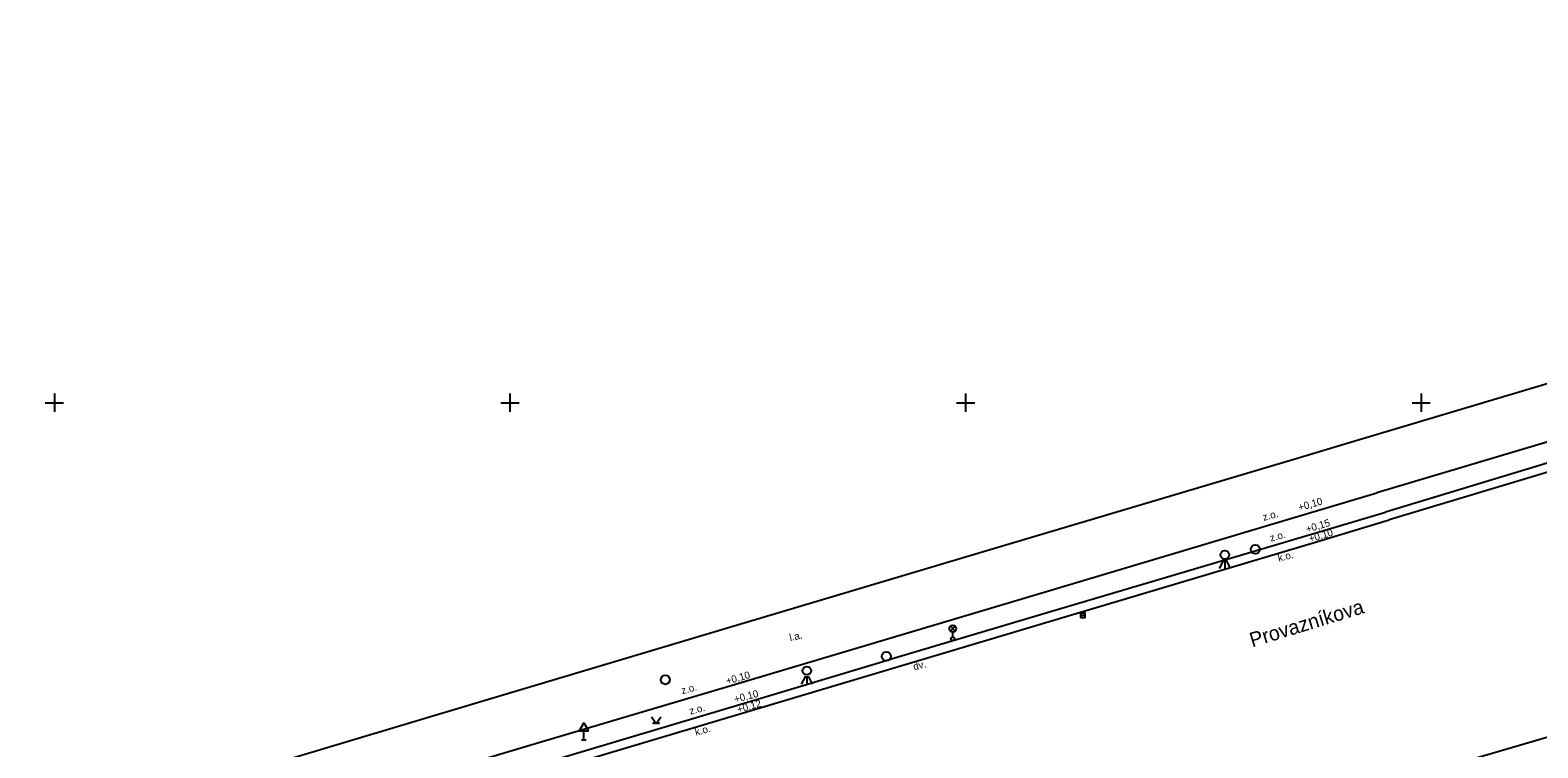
# Model space of a CAD drawing. Extents: x -597333 to -596488, y -1158921 to -1158644.
# Drawn here: x -597201.3 to -597118.6, y -1158843.9 to -1158804.6 of the extents above; entities that cross this region are included whole.
import ezdxf

# ---------------------------------------------------------------- set-up
doc = ezdxf.new("R2010")
doc.units = 0
for name, color, linetype in [('Vrstva 10', 7, 'Continuous'), ('Vrstva 14', 7, 'Continuous'), ('Vrstva 19', 7, 'Continuous'), ('Vrstva 25', 7, 'Continuous'), ('Vrstva 29', 7, 'Continuous'), ('Vrstva 42', 7, 'Continuous'), ('Vrstva 44', 7, 'Continuous'), ('Vrstva 49', 7, 'Continuous'), ('Vrstva 50', 7, 'Continuous'), ('Vrstva 62', 7, 'Continuous'), ('Vrstva 7', 7, 'Continuous')]:
    doc.layers.add(name, color=color, linetype=linetype)

msp = doc.modelspace()

# ---------------------------------------------------------------- linework, layer by layer
at = {"layer": 'Vrstva 10'}
for points in [[(-597131.858, -1158828.063), (-597128.696, -1158827.109), (-597091, -1158815.87), (-597089.946, -1158815.514), (-597071.273, -1158809.949), (-597053.2, -1158804.562)], [(-597163.188, -1158837.385), (-597148.28, -1158832.949), (-597131.858, -1158828.063)], [(-597187.728, -1158844.729), (-597176.909, -1158841.491), (-597163.188, -1158837.385)]]:
    msp.add_lwpolyline(points, dxfattribs=at)
at = {"layer": 'Vrstva 14'}
msp.add_lwpolyline([(-597167.23, -1158842.229), (-597166.98, -1158842.604), (-597166.73, -1158842.229)], dxfattribs=at)
for centre in [(-597167.105, -1158842.579), (-597166.855, -1158842.579)]:
    msp.add_circle(centre, 0.025, dxfattribs=at)
at = {"layer": 'Vrstva 19'}
for p, q in [((-597170.945, -1158842.56), (-597171.195, -1158842.993)), ((-597171.195, -1158842.993), (-597170.695, -1158842.993)), ((-597170.945, -1158842.56), (-597170.695, -1158842.993)), ((-597170.945, -1158843.493), (-597170.945, -1158842.993)), ((-597171.07, -1158843.493), (-597170.82, -1158843.493))]:
    msp.add_line(p, q, dxfattribs=at)
at = {"layer": 'Vrstva 25'}
msp.add_line((-597143.691, -1158836.663), (-597143.441, -1158836.663), dxfattribs=at)
msp.add_lwpolyline([(-597143.691, -1158836.788), (-597143.441, -1158836.788), (-597143.441, -1158836.538), (-597143.691, -1158836.538)], close=True, dxfattribs=at)
for centre in [(-597134.096, -1158833.04), (-597154.347, -1158838.916), (-597166.473, -1158840.201)]:
    msp.add_circle(centre, 0.25, dxfattribs=at)
at = {"layer": 'Vrstva 29'}
for p, q in [((-597150.834, -1158837.526), (-597150.57, -1158837.262)), ((-597150.566, -1158837.525), (-597150.83, -1158837.26)), ((-597150.702, -1158837.857), (-597150.702, -1158837.582))]:
    msp.add_line(p, q, dxfattribs=at)
for centre, radius in [((-597150.702, -1158837.394), 0.188), ((-597150.702, -1158837.957), 0.1)]:
    msp.add_circle(centre, radius, dxfattribs=at)
at = {"layer": 'Vrstva 44'}
for p, q in [((-597135.851, -1158833.636), (-597136.077, -1158834.088)), ((-597135.777, -1158833.638), (-597135.777, -1158834.088)), ((-597135.702, -1158833.636), (-597135.477, -1158834.088)), ((-597158.787, -1158839.997), (-597159.013, -1158840.449)), ((-597158.713, -1158839.999), (-597158.713, -1158840.449)), ((-597158.638, -1158839.997), (-597158.413, -1158840.449))]:
    msp.add_line(p, q, dxfattribs=at)
for centre in [(-597135.777, -1158833.343), (-597158.713, -1158839.704)]:
    msp.add_circle(centre, 0.234, dxfattribs=at)
at = {"layer": 'Vrstva 62'}
for p, q in [((-597200.5, -1158825), (-597199.5, -1158825)), ((-597200, -1158824.5), (-597200, -1158825.5)), ((-597175.5, -1158825), (-597174.5, -1158825)), ((-597175, -1158824.5), (-597175, -1158825.5)), ((-597150.5, -1158825), (-597149.5, -1158825)), ((-597150, -1158824.5), (-597150, -1158825.5)), ((-597125.5, -1158825), (-597124.5, -1158825)), ((-597125, -1158824.5), (-597125, -1158825.5))]:
    msp.add_line(p, q, dxfattribs=at)
at = {"layer": 'Vrstva 7'}
for p, q in [((-597089.33, -1158820.18), (-597126.764, -1158831.428)), ((-597131.055, -1158831.025), (-597127.43, -1158829.939)), ((-597130.836, -1158832.162), (-597126.956, -1158830.998)), ((-597130.742, -1158832.629), (-597126.764, -1158831.428)), ((-597154.776, -1158839.263), (-597153.829, -1158838.982)), ((-597162.336, -1158841.533), (-597154.776, -1158839.263))]:
    msp.add_line(p, q, dxfattribs=at)
for points in [[(-597089.968, -1158818.7), (-597101.13, -1158822.08), (-597103.06, -1158822.69), (-597127.43, -1158829.939)], [(-597089.55, -1158819.82), (-597100.83, -1158823.13), (-597102.75, -1158823.68), (-597126.956, -1158830.998)], [(-597162.814, -1158840.496), (-597146.541, -1158835.643), (-597131.055, -1158831.025)], [(-597153.829, -1158838.982), (-597146.007, -1158836.662), (-597130.836, -1158832.162)], [(-597162.076, -1158841.974), (-597145.959, -1158837.166), (-597130.742, -1158832.629)], [(-597188.741, -1158848.211), (-597173.228, -1158843.595), (-597162.814, -1158840.496)], [(-597188.396, -1158849.331), (-597172.992, -1158844.722), (-597162.336, -1158841.533)], [(-597201.328, -1158853.717), (-597172.609, -1158845.127), (-597162.075, -1158841.976)], [(-597112.65, -1158841.72), (-597113.192, -1158841.9), (-597118.55, -1158843.49), (-597126.354, -1158845.784)]]:
    msp.add_lwpolyline(points, dxfattribs=at)

# ---------------------------------------------------------------- texts
at = {"layer": 'Vrstva 42'}
msp.add_text('Provazníkova', height=0.8, rotation=17, dxfattribs=at).set_placement((-597134.271, -1158838.426))
at = {"layer": 'Vrstva 49'}
for s, rotation, p in [('z.o.', 15, (-597133.638, -1158831.487)), ('z.o.', 15, (-597133.244, -1158832.626)), ('k.o.', 15, (-597132.805, -1158833.731)), ('l.a.', 12.80009, (-597159.616, -1158838.087)), ('dv.', 15, (-597152.816, -1158839.688)), ('z.o.', 15, (-597165.542, -1158840.995)), ('z.o.', 15, (-597165.098, -1158842.119)), ('k.o.', 15, (-597164.792, -1158843.271))]:
    msp.add_text(s, height=0.4, rotation=rotation, dxfattribs=at).set_placement(p)
at = {"layer": 'Vrstva 50'}
for s, rotation, p in [('+0,10', 15.87762, (-597131.681, -1158830.946)), ('+0,15', 16.65768, (-597131.261, -1158832.141)), ('+0,10', 16.49351, (-597131.099, -1158832.669)), ('+0,10', 15.87762, (-597163.089, -1158840.47)), ('+0,10', 14.6923, (-597162.641, -1158841.473)), ('+0,12', 15.71759, (-597162.474, -1158842.032))]:
    msp.add_text(s, height=0.4, rotation=rotation, dxfattribs=at).set_placement(p)

doc.saveas('drawing.dxf')
